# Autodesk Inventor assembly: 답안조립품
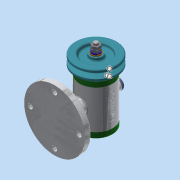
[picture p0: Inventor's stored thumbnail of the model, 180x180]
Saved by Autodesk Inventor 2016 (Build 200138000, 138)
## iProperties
Created: 2018-12
Part Number: 답안조립품
Material: 일반
Document SubType Name: Assembly
Designer: 3sil_cad018
Author: 3sil_cad018
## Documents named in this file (15)
- C:\Users\3sil_cad018\Desktop\481208V1003\답안조립품.iam
- C:\Users\3sil_cad018\Desktop\481208V1003\본체.ipt
- C:\Users\3sil_cad018\Desktop\481208V1003\V벨트풀리.ipt
- C:\Users\3sil_cad018\Desktop\481208V1003\고무캡.ipt
- C:\Users\3sil_cad018\Desktop\481208V1003\너트 M8.ipt
- 너트 M8.ipt
- C:\Users\3sil_cad018\Desktop\481208V1003\뒤커버.ipt
- C:\Users\3sil_cad018\Desktop\481208V1003\베어링 15 x 32 x 9.ipt
- C:\Users\3sil_cad018\Desktop\481208V1003\볼트 M4 x 12.ipt
- C:\Users\3sil_cad018\Desktop\481208V1003\스프링와셔 8.ipt
- C:\Users\3sil_cad018\Desktop\481208V1003\앞커버.ipt
- C:\Users\3sil_cad018\Desktop\481208V1003\오일 실 15 25 7.ipt
- C:\Users\3sil_cad018\Desktop\481208V1003\와셔 8x17.ipt
- C:\Users\3sil_cad018\Desktop\481208V1003\축.ipt
- C:\Users\3sil_cad018\Desktop\481208V1003\키 3 x 3 x 12.ipt
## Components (2 placed, 2 different names)
1. V벨트풀리:1
2. 고무캡:1
